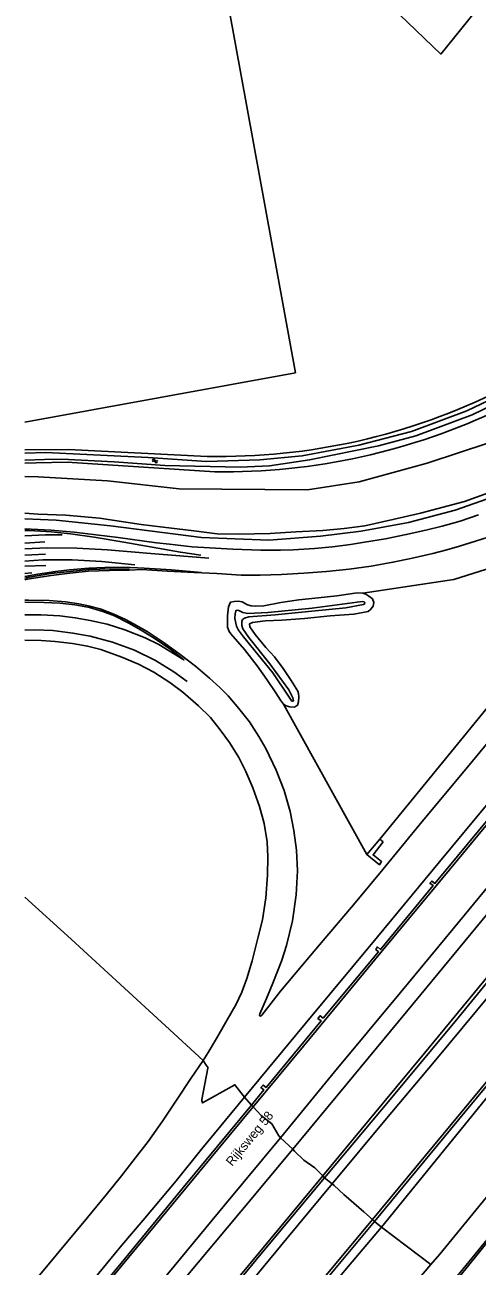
# Model space of a CAD drawing. Extents: x 135990 to 139000, y 393500 to 396000.
# Drawn here: x 136000 to 136123.7, y 394991 to 395330 of the extents above; entities that cross this region are included whole.
import ezdxf

# ---------------------------------------------------------------- set-up
doc = ezdxf.new("R2010")
doc.units = 0
for name, color, linetype in [('gg-afsc-erfafscheiding', 7, 'Continuous'), ('gg-anno-openbare ruimte label', 7, 'Continuous'), ('gg-knt-BGT kruinlijn', 7, 'Continuous'), ('gg-kntw-bovenkant insteek waterloop', 7, 'Continuous'), ('gg-kntw-waterlijn', 7, 'Continuous'), ('gt-bbg-plantopografie pand', 7, 'Continuous'), ('gt-symb-watersymbool', 7, 'Continuous'), ('gx-grn-maaiveld', 7, 'Continuous'), ('gx-knt-lijn weginrichtingselement', 7, 'Continuous')]:
    doc.layers.add(name, color=color, linetype=linetype)

# ---------------------------------------------------------------- blocks, each defined once
blk = doc.blocks.new('gt0-WA')
at = {"layer": 'gt-symb-watersymbool'}
for centre, start, end in [((-0.32, 0.02), 28.0725, 151.9275), ((0.43, 0.42), 208.0725, 331.9275), ((-0.32, -0.43), 28.0725, 151.9275), ((0.43, -0.03), 208.0725, 331.9275)]:
    blk.add_arc(centre, 0.425, start, end, dxfattribs=at)

msp = doc.modelspace()

# ---------------------------------------------------------------- linework, layer by layer
at = {"layer": 'gg-afsc-erfafscheiding'}
msp.add_lwpolyline([(136102.508, 395366.777), (136085.019, 395350.862), (136084.347, 395350.25), (136113.72, 395322.039), (136140.176, 395354.76), (136143.299, 395352.235), (136150.245, 395360.826), (136146.652, 395363.731), (136154.412, 395374.221)], dxfattribs=at)
at = {"layer": 'gg-knt-BGT kruinlijn'}
for p, q in [((136131.373, 395202.288), (136117.643, 395197.487)), ((136000, 395195.127), (136008.608, 395194.714)), ((136023.457, 395193.161), (136008.608, 395194.714)), ((136117.643, 395197.487), (136104.88, 395194.132)), ((136048.266, 395189.956), (136023.457, 395193.161)), ((136091.926, 395191.695), (136080.831, 395190.356)), ((136104.88, 395194.132), (136091.926, 395191.695)), ((136066.67, 395189.301), (136048.266, 395189.956)), ((136080.831, 395190.356), (136066.67, 395189.301))]:
    msp.add_line(p, q, dxfattribs=at)
for points in [[(136097.509, 395001.637), (136126.017, 395036.71), (136133.856, 395046.173), (136143.096, 395056.778), (136150.962, 395066.511)], [(136016.882, 394909.206), (136016.976, 394909.165), (136017.511, 394909.145), (136018.159, 394909.54), (136019.235, 394910.658), (136021.098, 394912.916), (136025.983, 394918.501), (136032.402, 394925.598), (136038.26, 394931.989), (136046.44, 394940.613), (136048.855, 394943.496), (136054.671, 394950.287), (136060.722, 394957.421), (136069.718, 394968.375), (136081.021, 394982.086), (136093.495, 394996.9), (136097.509, 395001.637)]]:
    msp.add_lwpolyline(points, dxfattribs=at)
at = {"layer": 'gg-kntw-bovenkant insteek waterloop'}
for points in [[(136000, 395213.99), (136011.94, 395214.082), (136049.84, 395212.153)], [(136000, 395210.306), (136003.11, 395210.4), (136011.62, 395210.56), (136051.96, 395207.913)]]:
    msp.add_lwpolyline(points, dxfattribs=at)
for centre, radius, start, end in [((136053.157, 395384.301), 172.18, 268.89615, 296.581), ((136054.026, 395384.555), 176.654, 269.32985, 295.52815)]:
    msp.add_arc(centre, radius, start, end, dxfattribs=at)
at = {"layer": 'gg-kntw-waterlijn'}
for points in [[(136000, 395213.027), (136005.708, 395213.243), (136033.724, 395211.863), (136049.641, 395210.782), (136064.274, 395211.234), (136075.82, 395212.301), (136091.29, 395215.226), (136105.749, 395218.964), (136120.838, 395224.644), (136130.744, 395229.304)], [(136130.609, 395227.543), (136122.298, 395223.551), (136106.872, 395217.811), (136096.723, 395215.022), (136077.837, 395211.215), (136066.897, 395209.542), (136058.867, 395209.223), (136038.323, 395209.671), (136024.43, 395210.66), (136010.09, 395211.374), (136005.356, 395211.337), (136000, 395211.169)]]:
    msp.add_lwpolyline(points, dxfattribs=at)
at = {"layer": 'gt-bbg-plantopografie pand'}
msp.add_lwpolyline([(136000, 395426.076), (136004.873, 395426.966), (136049.276, 395370.103), (136073.967, 395234.994), (136000, 395221.477)], dxfattribs=at)
at = {"layer": 'gx-grn-maaiveld'}
for p, q in [((136093.471, 395103.37), (136070.683, 395144.506)), ((136097.016, 395107.59), (136093.471, 395103.37)), ((136097.016, 395107.59), (136098.005, 395106.846)), ((136060.051, 395037.16), (136062.009, 395034.94)), ((136062.406, 395034.463), (136062.009, 395034.94)), ((136069.913, 395026.031), (136073.266, 395022.901)), ((136081.449, 395015.64), (136081.949, 395015.055)), ((136081.949, 395015.055), (136084.047, 395013.409)), ((136095.064, 395003.703), (136095.595, 395003.146)), ((136097.509, 395001.637), (136095.595, 395003.146)), ((136097.509, 395001.637), (136111.02, 394991.445))]:
    msp.add_line(p, q, dxfattribs=at)
for points in [[(136000, 395196.665), (136003.665, 395196.386), (136011.256, 395196.065), (136020.386, 395195.247), (136031.829, 395193.512), (136037.839, 395192.846), (136046.205, 395191.851), (136052.604, 395191.018), (136058.513, 395190.927), (136067.037, 395191.116), (136074.049, 395191.514), (136081.454, 395191.929), (136087.305, 395192.432), (136092.94, 395193.204), (136100.644, 395194.874), (136108.143, 395196.683), (136120.209, 395199.861), (136129.005, 395203.051), (136139.128, 395207.348), (136147.019, 395210.956), (136156.288, 395215.901), (136164.904, 395220.907), (136177.507, 395229.62)], [(136000, 395206.689), (136003.64, 395206.608), (136022.625, 395205.449), (136042.185, 395203.278), (136077.247, 395203.016), (136091.428, 395205.207), (136109.979, 395210.277), (136126.882, 395215.828), (136140.053, 395222.014), (136144.424, 395224.668)], [(136039.534, 394893.887), (136053.898, 394911.377), (136069.458, 394929.631), (136089.666, 394953.784), (136106.496, 394973.352), (136110.031, 394978.201), (136182.097, 395066.305), (136224.325, 395116.901), (136264.282, 395163.345), (136297.688, 395204.145), (136312.144, 395222.007)], [(136035.476, 394886.78), (136038.919, 394890.545), (136046.257, 394899.342), (136056.342, 394911.722), (136074.99, 394933.782), (136132.669, 395005.25), (136169.383, 395049.683), (136198.249, 395084.062), (136243.331, 395136.669), (136291.785, 395194.27), (136313.523, 395220.89)], [(136060.051, 395037.16), (136076.645, 395057.167), (136096.433, 395080.931), (136113.377, 395101.433), (136127.165, 395118.012), (136145.386, 395139.884), (136163.077, 395161.104), (136181.547, 395183.362), (136198.295, 395203.635), (136203.801, 395210.332)], [(136206.942, 395208.234), (136200.562, 395201.084), (136183.123, 395180.005), (136167.395, 395161.103), (136150.948, 395141.136), (136133.893, 395120.71), (136116.019, 395099.133), (136097.354, 395076.625), (136076.148, 395051.091), (136062.406, 395034.463)], [(136069.913, 395026.031), (136084.667, 395044.019), (136102.696, 395065.699), (136117.148, 395083.152), (136131.268, 395100.239), (136145.333, 395117.175), (136157.332, 395131.631), (136170.13, 395146.987), (136183.913, 395163.653), (136196.255, 395178.491), (136210.432, 395195.664), (136215.892, 395202.254)], [(136219.646, 395199.746), (136201.132, 395177.183), (136183.983, 395156.524), (136165.726, 395134.622), (136146.068, 395110.68), (136126.3, 395086.996), (136108.273, 395065.137), (136087.784, 395040.42), (136073.266, 395022.901)], [(136092.392, 395174.837), (136117.303, 395178.556), (136141.793, 395186.235), (136172.923, 395200.348), (136097.016, 395107.59)], [(136000, 395192.342), (136001.751, 395192.32), (136007.19, 395192.035), (136013.502, 395191.498), (136019.489, 395190.757), (136025.55, 395190.011), (136035.977, 395188.582), (136039.542, 395188.164), (136045.712, 395187.449), (136056.879, 395186.782), (136064.552, 395186.545), (136069.895, 395186.52), (136073.329, 395186.603), (136079.211, 395186.997), (136084.122, 395187.495), (136089.024, 395188.091), (136092.867, 395188.682), (136098.596, 395189.625), (136104.29, 395190.789), (136109.601, 395192.008), (136114.135, 395193.064), (136119.04, 395194.499), (136124.001, 395196.149)], [(136228.684, 395193.708), (136211.275, 395172.274), (136194.257, 395151.708), (136178.062, 395132.17), (136160.421, 395110.847), (136143.663, 395090.695), (136125.526, 395068.831), (136109.226, 395049.121), (136094.161, 395030.91), (136081.449, 395015.64)], [(136081.949, 395015.055), (136097.511, 395033.711), (136117.623, 395057.826), (136134.304, 395078.218), (136153.177, 395101.07), (136168.982, 395120.153), (136187.846, 395142.848), (136210.46, 395169.996), (136229.359, 395193.257)], [(136084.047, 395013.409), (136098.901, 395031.272), (136111.877, 395046.795), (136127.461, 395065.542), (136140.926, 395081.834), (136159.395, 395104.173), (136177.49, 395126.05), (136194.301, 395146.424), (136210.552, 395166.063), (136226.909, 395185.677), (136231.776, 395191.643)], [(136128.42, 395190.667), (136123.171, 395188.969), (136118.837, 395187.61), (136115.414, 395186.655), (136111.522, 395185.656), (136105.505, 395184.24), (136100.644, 395183.26), (136094.673, 395182.183), (136088.683, 395181.37), (136082.51, 395180.718), (136076.277, 395180.239), (136070.208, 395179.912), (136064.372, 395179.732), (136059.17, 395179.757), (136052.461, 395180.125), (136046.334, 395180.42), (136038.985, 395180.783), (136031.929, 395181.249), (136028.538, 395181.099)], [(136028.538, 395181.099), (136028.59, 395181.385), (136023.5, 395181.424), (136017.504, 395181.246), (136012.377, 395180.741), (136007.104, 395180.139), (136000.708, 395179.059), (136000, 395178.932)], [(136000, 395178.462), (136000.676, 395178.583), (136007.163, 395179.662), (136012.335, 395180.263), (136017.312, 395180.781), (136023.18, 395181.026), (136028.538, 395181.099)], [(136243.91, 395183.536), (136224.96, 395160.755), (136202.724, 395133.726), (136183.585, 395110.624), (136154.893, 395075.957), (136126.181, 395041.356), (136095.064, 395003.703)], [(136244.461, 395183.168), (136223.616, 395157.711), (136204.241, 395134.445), (136185.941, 395112.26), (136166.168, 395088.04), (136153.317, 395072.665), (136135.811, 395051.716), (136120.319, 395033.011), (136103.381, 395012.579), (136095.595, 395003.146)], [(136070.683, 395144.506), (136069.88, 395145.545), (136068.648, 395147.538), (136066.202, 395151.219), (136063.493, 395154.947), (136060.039, 395159.431), (136056.352, 395163.667), (136055.868, 395164.364), (136055.452, 395165.535), (136055.454, 395168.562), (136055.658, 395171.03), (136056.189, 395172.336), (136057.267, 395172.559), (136058.43, 395172.608), (136059.441, 395172.395), (136060.881, 395171.602), (136061.866, 395171.307), (136063.18, 395171.271), (136065.354, 395171.342), (136069.953, 395172.22), (136074.954, 395173.002), (136080.189, 395173.501), (136085.301, 395174.054)], [(136092.392, 395174.837), (136093.244, 395174.486), (136094.043, 395174.019), (136095.057, 395173.218), (136095.37, 395172.263), (136095.21, 395171.257), (136094.524, 395170.329), (136093.91, 395169.803), (136089.984, 395169.046), (136083.498, 395168.577), (136076.451, 395167.878), (136070.241, 395167.454), (136065.728, 395167.2), (136062.247, 395166.769), (136061.453, 395166.386), (136061.505, 395165.558), (136062.938, 395163.463), (136065.859, 395159.998), (136068.224, 395157.366), (136070.627, 395154.176), (136072.802, 395150.964), (136074.668, 395148.005), (136074.863, 395147.386), (136074.878, 395146.484), (136074.85, 395145.14), (136074.565, 395144.169), (136073.736, 395143.665), (136072.486, 395143.714), (136071.456, 395144.037), (136070.683, 395144.506)], [(136092.392, 395174.837), (136090.878, 395174.899), (136085.301, 395174.054)], [(136000, 395172.846), (136001.002, 395172.895), (136006.616, 395172.756), (136011.122, 395172.39), (136014.73, 395171.85), (136017.805, 395171.251), (136020.568, 395170.503), (136024.328, 395169.05), (136027.521, 395167.567), (136029.721, 395166.448), (136033.432, 395164.298), (136038.084, 395161.196), (136042.458, 395158.018), (136046.688, 395154.812), (136050.466, 395151.6), (136053.283, 395148.985), (136055.56, 395146.712), (136058.553, 395143.248), (136061.397, 395139.61), (136064.004, 395135.676), (136065.88, 395132.387), (136068.701, 395126.409), (136070.9, 395120.852), (136072.511, 395115.169), (136073.59, 395109.997), (136074.304, 395104.578), (136074.591, 395098.907), (136074.196, 395092.383), (136073.155, 395085.258), (136071.572, 395078.556), (136070.151, 395074.231), (136067.801, 395068.281), (136066.099, 395064.039), (136064.282, 395059.904), (136064.152, 395059.464), (136064.259, 395059.32), (136064.421, 395059.244), (136064.613, 395059.3), (136064.775, 395059.482), (136069.927, 395066.092), (136075.62, 395072.928), (136080.578, 395078.755), (136090.343, 395090.234), (136097.843, 395099.342), (136108.655, 395112.381), (136120.566, 395126.712), (136130.132, 395138.31)], [(136061.279, 395168.325), (136060.06, 395168.012), (136059.492, 395167.6), (136059.309, 395167.085), (136059.298, 395165.956), (136059.575, 395165.009), (136061.226, 395162.683), (136066.963, 395155.48), (136072.171, 395148.397), (136073.311, 395146.204), (136073.491, 395145.41), (136073.319, 395145.301), (136073.031, 395145.334), (136072.463, 395146.151), (136067.807, 395152.994), (136059.807, 395162.858), (136058.426, 395164.712), (136057.852, 395165.793), (136057.455, 395167.866), (136057.52, 395169.163), (136057.661, 395169.999), (136058.072, 395170.151), (136058.535, 395170.095), (136059.586, 395169.529), (136061.007, 395169.222), (136066.413, 395169.501), (136078.602, 395170.714), (136092.248, 395172.496), (136092.785, 395172.407), (136092.975, 395172.233), (136092.937, 395171.995), (136092.56, 395171.704), (136087.765, 395170.795), (136078.499, 395169.901), (136068.478, 395168.852), (136061.279, 395168.325)], [(136260.813, 395172.244), (136255.971, 395166.413), (136245.218, 395153.46), (136223.92, 395127.466), (136201.544, 395101.061), (136178.81, 395074.393), (136157.717, 395048.771), (136136.065, 395021.821), (136113.42, 394994.267), (136111.02, 394991.445)], [(136048.804, 395047.144), (136050.157, 395049.347), (136052.381, 395053.174), (136055.32, 395058.246), (136057.649, 395062.36), (136059.324, 395065.797), (136060.738, 395069.577), (136062.158, 395074.398), (136063.729, 395080.594), (136064.947, 395085.596), (136065.885, 395091.57), (136066.362, 395097.783), (136066.421, 395102.806), (136066.225, 395106.83), (136065.415, 395111.901), (136064.141, 395116.482), (136062.352, 395121.6), (136060.388, 395126.121), (136058.466, 395129.874), (136055.921, 395133.986), (136053.418, 395137.506), (136050.753, 395140.791), (136047.528, 395144.056), (136043.228, 395147.767), (136039.687, 395150.413), (136035.268, 395153.191), (136031.036, 395155.357), (136026.561, 395157.349), (136020.804, 395159.415), (136017.14, 395160.329), (136013.005, 395161.079), (136008.321, 395161.615), (136004.501, 395161.901), (136000, 395161.924)], [(136062.009, 395034.94), (136065.354, 395039.104), (136064.545, 395039.732), (136065.124, 395040.425), (136065.955, 395039.757), (136081.016, 395058.011), (136080.144, 395058.632), (136080.728, 395059.346), (136081.554, 395058.708), (136096.719, 395076.822), (136095.946, 395077.481), (136096.45, 395078.161), (136097.262, 395077.457), (136111.615, 395094.912), (136110.761, 395095.547), (136111.243, 395096.148), (136112.127, 395095.492), (136127.108, 395113.617)], [(136098.005, 395106.846), (136095.188, 395103.292), (136097.548, 395101.466), (136096.923, 395100.616), (136093.471, 395103.37)], [(136000, 395091.784), (136000.011, 395091.774), (136012.63, 395080.245), (136026.121, 395067.92), (136038.502, 395056.609), (136048.804, 395047.144)], [(136000, 394983.663), (136017.126, 395004.283), (136022.242, 395010.482), (136026.435, 395015.671), (136029.576, 395019.66), (136033.725, 395025.053), (136037.682, 395030.611), (136041.482, 395036.313), (136045.428, 395042.239), (136048.804, 395047.144)], [(136048.804, 395047.144), (136049.621, 395045.852), (136050.088, 395045.112), (136050.068, 395045.012), (136048.356, 395036.528), (136048.426, 395036.244), (136048.599, 395035.543), (136057.445, 395040.518), (136059.686, 395037.583), (136060.051, 395037.16)], [(136000, 394964.559), (136011.367, 394978.347), (136016.081, 394983.948), (136026.563, 394996.665), (136032.348, 395003.527), (136041.335, 395014.293), (136048.374, 395022.971), (136060.051, 395037.16)], [(136000, 394959.917), (136009.485, 394971.401), (136026.328, 394991.803), (136043.383, 395012.516), (136062.009, 395034.94)], [(136000, 394959.166), (136007.395, 394968.14), (136021.341, 394984.86), (136035.393, 395001.79), (136052.7, 395022.772), (136062.406, 395034.463)], [(136062.406, 395034.463), (136064.6, 395032.149), (136067.503, 395029.825), (136069.447, 395026.566), (136069.913, 395026.031)], [(136000, 394941.415), (136006.069, 394948.955), (136020.984, 394966.945), (136037.36, 394986.76), (136054.727, 395007.711), (136069.913, 395026.031)], [(136000, 394934.893), (136013.636, 394951.272), (136029.301, 394970.121), (136043.687, 394987.546), (136059.028, 395005.929), (136073.266, 395022.901)], [(136081.449, 395015.64), (136079.241, 395017.857), (136076.26, 395019.908), (136073.735, 395022.398), (136073.266, 395022.901)], [(136081.449, 395015.64), (136075.705, 395008.751), (136058.538, 394987.926), (136041.654, 394967.512), (136024.516, 394946.959), (136006.699, 394925.197), (136005.666, 394923.699), (136005.928, 394923.225)], [(136081.949, 395015.055), (136064.564, 394994.221), (136043.64, 394968.913), (136027.518, 394949.529), (136005.928, 394923.225)], [(136084.047, 395013.409), (136071.649, 394998.561), (136055.714, 394979.173), (136038.699, 394958.695), (136022.11, 394938.605), (136007.405, 394920.912), (136006.992, 394921.49), (136006.78, 394921.226)], [(136095.064, 395003.703), (136092.727, 395005.849), (136089.917, 395008.189), (136087.217, 395010.564), (136084.557, 395013.038), (136084.047, 395013.409)], [(136095.064, 395003.703), (136081.493, 394987.415), (136069.297, 394972.601), (136061.414, 394963.005), (136052.358, 394952.098), (136048.476, 394947.627), (136044.951, 394943.558), (136042.379, 394940.575), (136038.844, 394936.83), (136035.688, 394933.511), (136031.316, 394928.825), (136028.271, 394925.441), (136024.62, 394921.382), (136014.295, 394908.925), (136014.488, 394908.494)], [(136095.595, 395003.146), (136084.688, 394990.066), (136074.26, 394977.556), (136065.523, 394966.955), (136058.783, 394958.889), (136052.44, 394951.315), (136049.286, 394947.486), (136044.693, 394942.167), (136042.28, 394939.402), (136040.155, 394937.122), (136037.23, 394934.105), (136033.39, 394930), (136029.009, 394925.186), (136024.32, 394920.028), (136020.793, 394915.8), (136016.324, 394910.735)], [(136111.02, 394991.445), (136091.235, 394968.181), (136076.69, 394950.842), (136064.67, 394937.5), (136055.417, 394927.329), (136050.473, 394921.986), (136044.721, 394915.828), (136039.704, 394910.733), (136039.225, 394910.396), (136033.078, 394903.835), (136032.473, 394901.987), (136033.242, 394900.681), (136034.392, 394899.513), (136037.328, 394896.738), (136038.979, 394894.391), (136039.534, 394893.887)]]:
    msp.add_lwpolyline(points, dxfattribs=at)
at = {"layer": 'gx-knt-lijn weginrichtingselement'}
for p, q in [((136000, 395188.422), (136005.511, 395188.774)), ((136000, 395185.195), (136005.697, 395185.476)), ((136000, 395182.127), (136005.704, 395182.311)), ((136000, 395180.173), (136001.886, 395180.339))]:
    msp.add_line(p, q, dxfattribs=at)
for points in [[(136000, 395191.883), (136001.244, 395191.869), (136007.23, 395191.535), (136012.518, 395191.017), (136018.936, 395190.113), (136027.062, 395188.745), (136034.804, 395187.391), (136042.549, 395185.982), (136048.103, 395185.14)], [(136000, 395190.481), (136005.675, 395190.729), (136010.175, 395190.737)], [(136000, 395186.898), (136006.144, 395187.176), (136014.25, 395187.115), (136022.631, 395186.643), (136034.454, 395185.594), (136050.272, 395184.312)], [(136000, 395183.566), (136004.919, 395183.866), (136012.958, 395183.91), (136021.029, 395183.403), (136030.061, 395182.49)], [(136000, 395179.357), (136003.55, 395180.02), (136008.406, 395180.755), (136012.216, 395181.211), (136017.514, 395181.642), (136021.907, 395181.765), (136027.075, 395181.853), (136032.59, 395181.668), (136040.093, 395181.187), (136048.229, 395180.479)], [(136000, 395172.332), (136005.236, 395172.269), (136009.581, 395172.029), (136013.68, 395171.579), (136017.689, 395170.916), (136021.354, 395169.777), (136024.532, 395168.592), (136028.465, 395166.627), (136031.848, 395164.726), (136035.635, 395162.319), (136039.627, 395159.588), (136043.517, 395156.572), (136036.595, 395160.815), (136032.902, 395162.619), (136027.354, 395164.806), (136022.551, 395166.3), (136017.864, 395167.351), (136013.769, 395168.093), (136009.541, 395168.602), (136004.449, 395168.874), (136000, 395168.838)], [(136000, 395164.705), (136002.616, 395164.764), (136007.693, 395164.557), (136013.168, 395163.911), (136017.89, 395163.013), (136023.935, 395161.45), (136030.003, 395159.201), (136035.712, 395156.367), (136040.776, 395153.276), (136044.377, 395150.644)]]:
    msp.add_lwpolyline(points, dxfattribs=at)

# ---------------------------------------------------------------- block references
at = {"layer": 'gt-symb-watersymbool', "rotation": -3.7264258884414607}
msp.add_blockref('gt0-WA', (136035.5, 395210.923), dxfattribs=at)

# ---------------------------------------------------------------- texts
at = {"layer": 'gg-anno-openbare ruimte label'}
msp.add_text('Rijksweg 58', height=2.5, rotation=50.5, dxfattribs=at).set_placement((136056.675, 395018.102))

doc.saveas('drawing.dxf')
